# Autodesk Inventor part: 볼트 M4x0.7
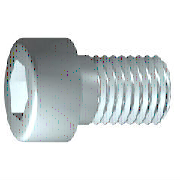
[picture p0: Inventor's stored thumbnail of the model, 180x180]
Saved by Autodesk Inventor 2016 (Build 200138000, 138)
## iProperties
IsCustomPart: 1
Created: 2015-10
Part Number: 볼트 M4x0.7
Material: 스테인리스강
Description: 6각머리 태핑 나사
Document SubType Name: Modeling
Standard: KS B 1003
Designer: mdu
Standards Organization: KS
Language: ko-KR
Size Designation: M 4 x 16
Categories: <MemberInstance><Categories><Category DisplayName="조임쇠" InternalName="e4da775c-781d-43d5-af7c-5136215cf5a6" Mnemonic="FSTN"><Category DisplayName="볼트" InternalN
Density: 8.08 g/cm^3
Mass: 2.70334 g
Surface Area: 3.81118 cm^2
Volume: 0.334572 cm^3
Appearance: 반광택
Author: mdu
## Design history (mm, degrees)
sketch "스케치1"
  geometry: L1 (-1, 0)-(16, 0); L2 (16, 0)-(16, 2); L3 (16, 2)-(1.75, 2); L4 (1.75, 2)-(1.32, 2); L5 (1.32, 2)-(0, 2); L6 (0, 2)-(0, 3.5); L7 (0, 3.5)-(-4, 3.5); L8 (-4, 3.5)-(-4, 1.732); L9 (-4, 1.732)-(-2, 1.732); L10 (-2, 1.732)-(-1, 0); L11 (-8, 0)-(20, 0) reference; L12 (0, -0.7)-(0, 4.2) reference; L13 (1.75, 2)-(0, 2)
  constraints: 22 end point, 6 parallel, 2 collinear, 2 perpendicular, 1 horizontal, 1 point on line
  dimensions: "d1" = 14.25 distance from line of L3.end L2 (= GEL); "d2" = 0.42952 distance of L4.end L3.end (computed from GAL); "d3" = 4 distance between parallel lines of L8 L6 (= KOH); "d4" = 2 distance of L8.end L9.end (= INTI); "d5" = 60 deg angle of L10 L1; "d6" = 4 diameter of L3 L1 (= GD); "d7" = 4 diameter of L5 L1 (= BDM); "d8" = 3.4641 diameter of L9 L1 (= 1.1547 x SW); "d9" = 7 diameter of L7 L1 (= KOD); "d26" = 16 distance between parallel lines of L12 L2 (= NLG)
revolve "본체" sketch "스케치1" stored, may be unused: angle "d10" = 90 deg
sketch "스케치2"
  geometry: L1 (0, -4.9)-(0, 4.9) reference; L2 (-4.9, 0)-(4.9, 0) reference; L3 (1.732, 0)-(0.866, -1.5); L4 (0.866, -1.5)-(-0.866, -1.5); L5 (-0.866, -1.5)-(-1.732, 0); L6 (-1.732, 0)-(-0.866, 1.5); L7 (-0.866, 1.5)-(0.866, 1.5); L8 (0.866, 1.5)-(1.732, 0); 2 further points
  constraints: 12 end point, 1 coincident, 1 horizontal alignment, 1 point on line, 12 other
extrude "슬롯" join sketch "스케치2" stored distance "d11" = 10; taper "d12" = 0 deg
workplane "Work Plane1"
fillet "Fillet2" dims "d30" = 0.1 (= R)
body "Solid1"
fillet "모깎기1" dims "d17" = 0.4 (= RR)
feature "스레드" dims "d13" = 14.25 (= GEL), "d14" = 0
chamfer "모따기1" distance "d15" = 0.42941 (= -0.5 x SPD + 0.5 x GD); stored, may be unused: second distance "d16" = 0.42941 (= GUL), angle "d27" = 45 deg
other parameters: "GD" = 4 (= NND) [user parameter; used in 2 equation terms], "NLG" = 16 [user parameter; used in 1 equation term], "GEL" = 14.25 [user parameter; used in 2 equation terms], "KOD" = 7 [user parameter; used in 1 equation term], "KOH" = 4 [user parameter; used in 1 equation term], "INTI" = 2 [user parameter; used in 1 equation term], "GAL" = 0.42941 (= 0.61345 x PTC) [user parameter; used in 1 equation term], "GUL" = 0.42941 (= 0.61345 x PTC) [user parameter; used in 1 equation term], "BDM" = 4 (= NND) [user parameter; used in 1 equation term], "SW" = 3 [user parameter; used in 2 equation terms], "RR" = 0.4 [user parameter; used in 1 equation term], "SPD" = 3.14117 (= NND - 1.2269 x PTC) [user parameter; used in 1 equation term], "d19" = 0, "d28" = 0, "d29" = 0, "R" = 0.1 [user parameter; used in 1 equation term], "PHH" = 0.2 [user parameter], "GD1" = 3.14117 (= THREADDIA - 1.2269 x PTC) [user parameter], "THREADDIA" = 4 [user parameter; used in 1 equation term], "FAWI" = 45 deg [user parameter], "TPU" = 14.28571 (computed from PTC) [user parameter], "PTC" = 0.7 [user parameter; used in 5 equation terms], "NND" = 4 [user parameter; used in 3 equation terms], "TOA" = 30 deg [user parameter], "E0" = 3.465 (= 1.155 x SW) [user parameter]
